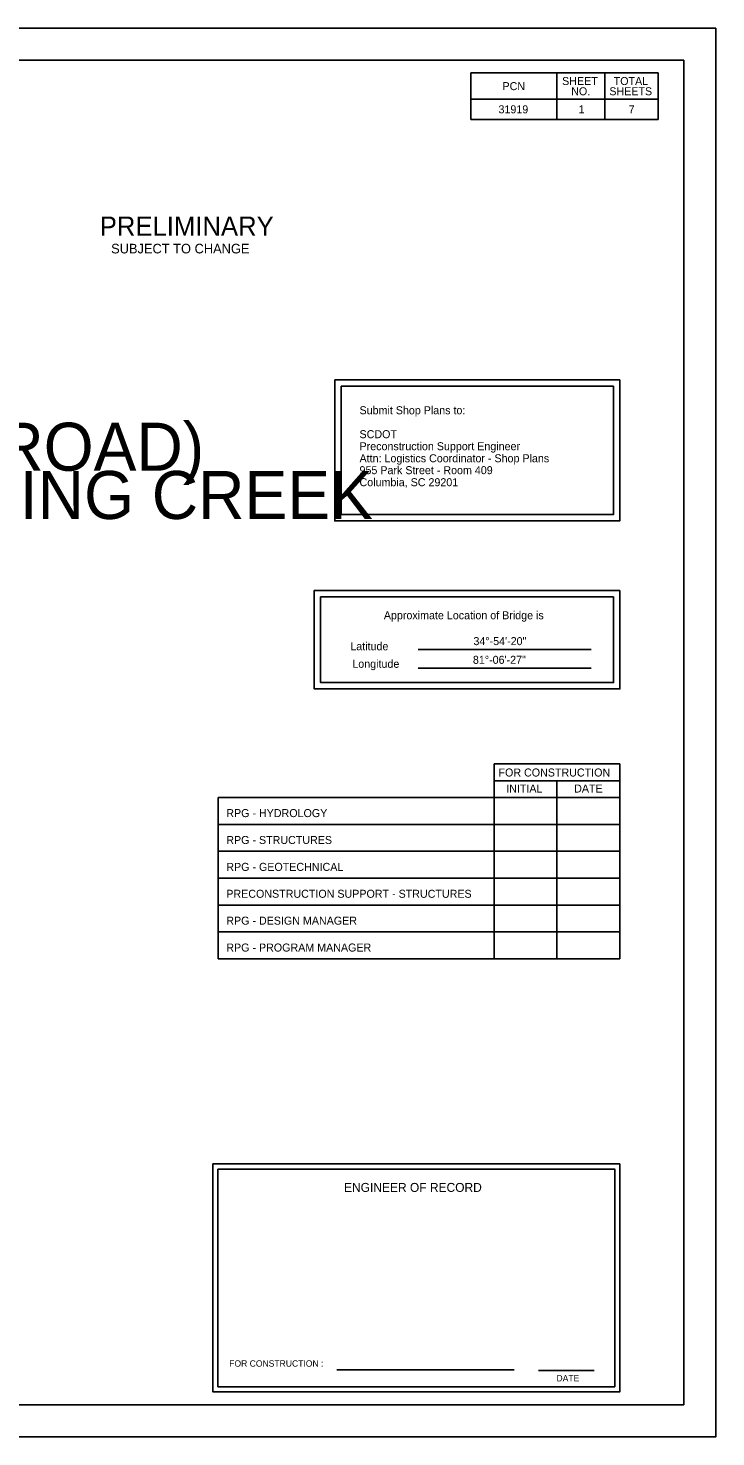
# Model space of a CAD drawing. Extents: x 297202 to 299002, y -166223 to -165123.
# Drawn here: x 298464 to 299002, y -166223 to -165123 of the extents above; entities that cross this region are included whole.
import ezdxf

# ---------------------------------------------------------------- set-up
doc = ezdxf.new("R2010")
doc.units = 0
for name, color, linetype in [('BR_BORDER LINES', 7, 'Continuous'), ('BR_CONCRETE', 7, 'Continuous'), ('BR_DETAILS', 7, 'Continuous'), ('BR_TEXT', 7, 'Continuous'), ('RD_SHT_IplotShp', 7, 'Continuous')]:
    doc.layers.add(name, color=color, linetype=linetype)

msp = doc.modelspace()

# ---------------------------------------------------------------- linework, layer by layer
at = {"layer": 'BR_BORDER LINES'}
for p, q in [((297201.6, -165123), (299001.6, -165123)), ((297301.6, -165148), (298976.6, -165148)), ((298976.6, -166198), (298976.6, -165148)), ((298976.6, -165206.3), (298976.6, -165181.4)), ((298976.6, -165558.7), (298976.6, -165206.3)), ((297301.6, -166198), (298976.6, -166198)), ((297201.6, -166223), (299001.6, -166223))]:
    msp.add_line(p, q, dxfattribs=at)
at = {"layer": 'BR_DETAILS'}
for p, q in [((298810.3, -165194.2), (298810.3, -165158)), ((298956.6, -165158), (298810.3, -165158)), ((298877.3, -165194.2), (298877.3, -165158)), ((298914.8, -165158), (298914.8, -165194.2)), ((298956.6, -165194.2), (298956.6, -165158)), ((298810.3, -165178.5), (298956.6, -165178.5)), ((298810.3, -165194.2), (298956.6, -165194.2)), ((298769, -165608.3), (298904.2, -165608.3)), ((298769, -165622.8), (298904.2, -165622.8)), ((298828.3, -165697.6), (298926.6, -165697.6)), ((298828.3, -165697.6), (298828.3, -165849.8)), ((298926.6, -165697.6), (298926.6, -165849.8)), ((298828.3, -165710.7), (298926.6, -165710.7)), ((298877.4, -165710.7), (298877.4, -165849.8)), ((298612.8, -165849.8), (298612.8, -165723.8)), ((298612.8, -165723.8), (298926.6, -165723.8)), ((298612.8, -165744.8), (298926.6, -165744.8)), ((298612.8, -165765.8), (298926.6, -165765.8)), ((298612.8, -165786.8), (298926.6, -165786.8)), ((298612.8, -165807.8), (298926.6, -165807.8)), ((298612.8, -165828.8), (298926.6, -165828.8)), ((298612.8, -165849.8), (298926.6, -165849.8)), ((298705.4, -166170.8), (298844, -166170.8)), ((298863.1, -166171.4), (298906.6, -166171.4))]:
    msp.add_line(p, q, dxfattribs=at)
for points in [[(298703.9, -165397.7), (298926.6, -165397.7), (298926.6, -165507.8), (298703.9, -165507.8)], [(298708.9, -165402.7), (298921.6, -165402.7), (298921.6, -165502.8), (298708.9, -165502.8)], [(298926.7, -165562.1), (298687.8, -165562.1), (298687.8, -165639), (298926.7, -165639)], [(298921.7, -165567.1), (298692.8, -165567.1), (298692.8, -165634), (298921.7, -165634)], [(298608.6, -166010), (298926.6, -166010), (298926.6, -166188), (298608.6, -166188)], [(298612.6, -166014), (298922.6, -166014), (298922.6, -166184), (298612.6, -166184)]]:
    msp.add_lwpolyline(points, close=True, dxfattribs=at)
at = {"layer": 'RD_SHT_IplotShp'}
msp.add_lwpolyline([(297201.6, -165123.1), (299001.6, -165123.1), (299001.6, -166223.1), (297201.6, -166223.1)], close=True, dxfattribs=at)

# ---------------------------------------------------------------- texts
at = {"layer": 'BR_CONCRETE'}
for s, height, p in [('PRELIMINARY', 15, (298520.2, -165285.1)), ('SUBJECT TO CHANGE', 7.5, (298529.1, -165298.9))]:
    msp.add_text(s, height=height, dxfattribs=at).set_placement(p)
at = {"layer": 'BR_DETAILS'}
for s, height, p in [('SHEET', 6.25, (298881.5, -165167.4)), ('TOTAL', 6.25, (298921.8, -165167.4)), ('PCN', 6.25, (298834.9, -165171.4)), ('NO.', 6.25, (298888.6, -165175.4)), ('SHEETS', 6.25, (298918.4, -165175.4)), ('Submit Shop Plans to:', 6.25, (298723.2, -165424.5)), ('ROUTE S-103 (OAK PARK ROAD) ', 37.5, (297816, -165468.6)), ('SCDOT', 6.25, (298723.2, -165443.2)), ('Preconstruction Support Engineer', 6.25, (298723.2, -165452.6)), ('Attn: Logistics Coordinator - Shop Plans', 6.25, (298723.2, -165462)), ('REPLACE BRIDGE OVER FISHING CREEK', 37.5, (297733.3, -165506.3)), ('955 Park Street - Room 409', 6.25, (298723.2, -165471.3)), ('Columbia, SC 29201', 6.25, (298723.2, -165480.7)), ('Approximate Location of Bridge is', 6.25, (298742.2, -165584.6)), ('Latitude', 6.25, (298716, -165608.8)), ('Longitude', 6.25, (298717.6, -165622.5)), ('RPG - HYDROLOGY ', 6.248, (298619.1, -165739.1)), ('RPG - STRUCTURES', 6.248, (298619.1, -165760.1)), ('RPG - GEOTECHNICAL', 6.248, (298619.1, -165781.1)), ('PRECONSTRUCTION SUPPORT - STRUCTURES', 6.248, (298619.1, -165802.1)), ('RPG - DESIGN MANAGER', 6.248, (298619.1, -165823.1)), ('RPG - PROGRAM MANAGER', 6.248, (298619.1, -165844.1)), ('ENGINEER OF RECORD', 7, (298711.1, -166031.8)), ('FOR CONSTRUCTION :', 5, (298621.4, -166168.3)), ('DATE', 5, (298877.1, -166179.8))]:
    msp.add_text(s, height=height, dxfattribs=at).set_placement(p)
for s, height, p in [('FOR CONSTRUCTION', 6.248, (298831.8, -165707.4)), ('INITIAL', 6.25, (298837.8, -165719.9)), ('DATE', 6.25, (298890.9, -165719.9))]:
    msp.add_text(s, height=height, rotation=360, dxfattribs=at).set_placement(p)
at = {"layer": 'BR_TEXT'}
for s, p in [('31919', (298831.8, -165189.5)), ('1', (298894.4, -165189.5)), ('7', (298933.5, -165189.5)), ('34%%d-54\'-20"', (298812.2, -165604.8)), ('81%%d-06\'-27"', (298811.8, -165619.4))]:
    msp.add_text(s, height=6.25, dxfattribs=at).set_placement(p)

doc.saveas('drawing.dxf')
